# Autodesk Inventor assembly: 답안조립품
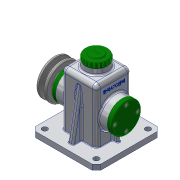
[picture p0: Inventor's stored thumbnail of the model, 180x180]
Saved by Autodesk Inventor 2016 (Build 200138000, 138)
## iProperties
Created: 2018-10
Part Number: 답안조립품
Material: 일반
Document SubType Name: Assembly
Designer: user
Author: user
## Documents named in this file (14)
- C:\Users\user\Desktop\481016V1012\답안조립품.iam
- C:\Users\user\Desktop\481016V1012\본체.ipt
- C:\Users\user\Desktop\481016V1012\베어링 15 x 35 x 11.ipt
- C:\Users\user\Desktop\481016V1012\뒤커버.ipt
- C:\Users\user\Desktop\481016V1012\앞커버.ipt
- C:\Users\user\Desktop\481016V1012\오일실 15 25 7.ipt
- C:\Users\user\Desktop\481016V1012\볼트 M4 x 10.ipt
- C:\Users\user\Desktop\481016V1012\축.ipt
- C:\Users\user\Desktop\481016V1012\키 5 x 5 x 14.ipt
- C:\Users\user\Desktop\481016V1012\멈춤링 15 x 1.ipt
- C:\Users\user\Desktop\481016V1012\와셔.ipt
- C:\Users\user\Desktop\481016V1012\V-벨트풀리.ipt
- C:\Users\user\Desktop\481016V1012\볼트 M6 x 12.ipt
- C:\Users\user\Desktop\481016V1012\상부캡.ipt
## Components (1 placed, 1 different names)
1. V-벨트풀리:1 — 각도:1
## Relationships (1: Angle 1)
- 각도:1 [Angle]: V-벨트풀리:1
